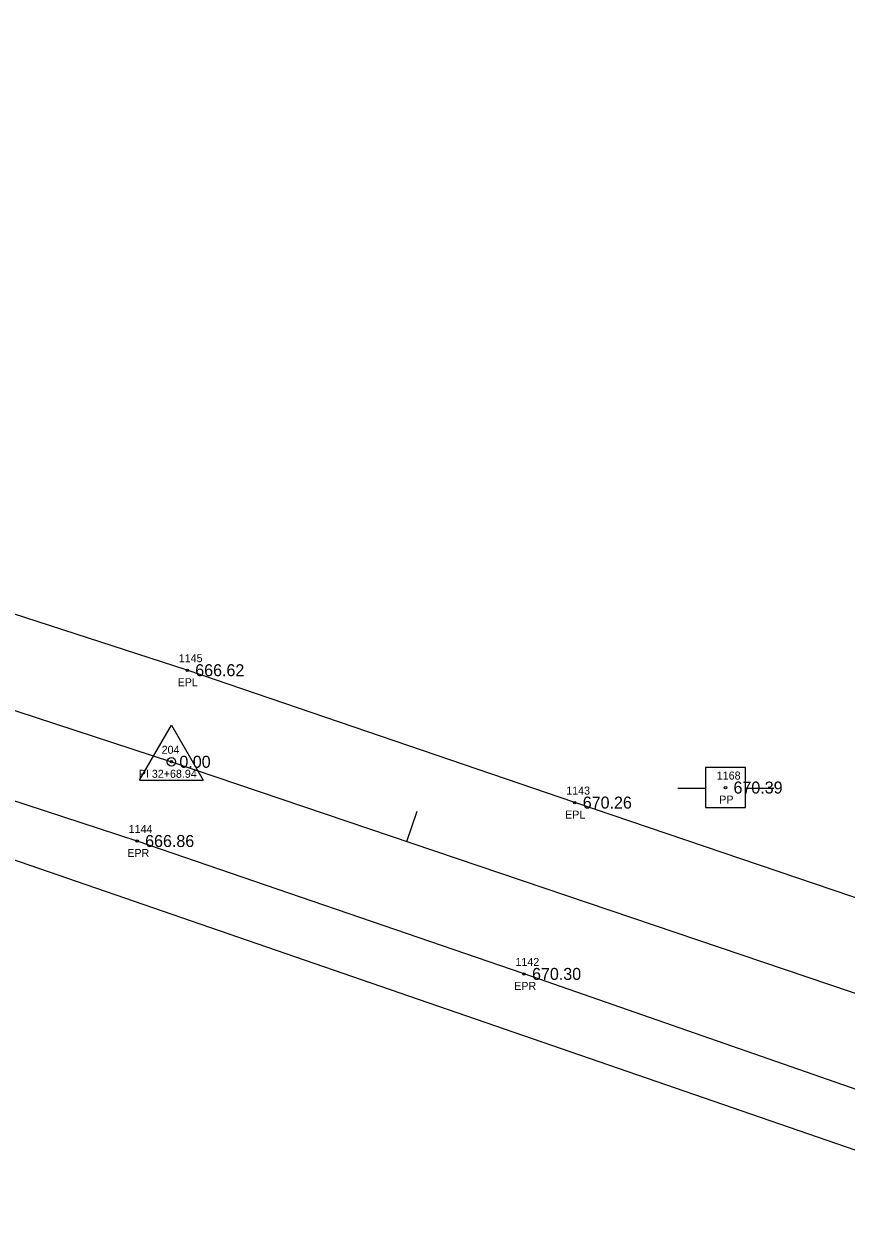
# Model space of a CAD drawing. Extents: x 1655137 to 1657928, y 1003994 to 1005407.
# Drawn here: x 1656606.1 to 1656708.9, y 1004485.2 to 1004634.6 of the extents above; entities that cross this region are included whole.
import ezdxf

# ---------------------------------------------------------------- set-up
doc = ezdxf.new("R2010")
doc.units = 0
for name, color, linetype in [('RD_EX_Road', 7, 'Continuous'), ('RD_EX_Road_txCode', 7, 'Continuous'), ('RD_EX_TX_Road_ELEV', 7, 'Continuous'), ('RD_EX_UT', 7, 'Continuous'), ('RD_EX_UT_txCode', 7, 'Continuous'), ('RD_EX_VEG', 7, 'Continuous'), ('RD_HC_Cl', 7, 'Continuous'), ('RD_HC_Data', 7, 'Continuous'), ('RD_HC_Data_Tic', 7, 'Continuous'), ('RD_HC_Survey_ELEV', 7, 'Continuous'), ('RD_HC_txCode', 7, 'Continuous'), ('RD_SMD_Locator', 7, 'Continuous')]:
    doc.layers.add(name, color=color, linetype=linetype)

msp = doc.modelspace()

# ---------------------------------------------------------------- linework, layer by layer
at = {"layer": 'RD_EX_Road'}
for points in [[(1657064.39, 1004409.09), (1657015.67, 1004424.64), (1656965.82, 1004440.6), (1656917.99, 1004455.95), (1656868.5, 1004471.86), (1656826.53, 1004486.06), (1656801.74, 1004494.51), (1656772.14, 1004504.27), (1656723.45, 1004520.92), (1656674.94, 1004537.34), (1656626.5, 1004553.88), (1656578.27, 1004569.52), (1656529.18, 1004584.75), (1656481.5, 1004600.51), (1656432.67, 1004617.14), (1656404.34, 1004625.82)], [(1657057.77, 1004388.92), (1657009.7, 1004404.08), (1656958.18, 1004419.84), (1656956.49, 1004419.67), (1656924.83, 1004429.55), (1656916.51, 1004432.8), (1656911.19, 1004434.68), (1656862.46, 1004450.21), (1656813.53, 1004466.42), (1656765.51, 1004482.33), (1656716.81, 1004499.14), (1656668.6, 1004515.93), (1656620.24, 1004532.54), (1656571.72, 1004548.37), (1656523.3, 1004563.77), (1656474.37, 1004580.29), (1656426.43, 1004596.82), (1656398.22, 1004606.78)]]:
    msp.add_lwpolyline(points, dxfattribs=at)
at = {"layer": 'RD_EX_UT'}
for p, q in [((1656696.27, 1004541.73), (1656691.27, 1004541.73)), ((1656691.27, 1004541.73), (1656691.27, 1004536.73)), ((1656696.27, 1004536.73), (1656696.27, 1004541.73)), ((1656687.84, 1004539.16), (1656691.31, 1004539.16)), ((1656696.2, 1004539.16), (1656699.84, 1004539.16)), ((1656691.27, 1004536.73), (1656696.27, 1004536.73))]:
    msp.add_line(p, q, dxfattribs=at)
at = {"layer": 'RD_EX_VEG'}
msp.add_lwpolyline([(1656891.08, 1004405.37), (1656915.13, 1004420.4), (1656763.49, 1004475.48), (1656570, 1004542.2), (1656467.82, 1004565.09), (1656367.55, 1004594.62), (1656280.9, 1004634.63), (1656273.57, 1004608.65)], dxfattribs=at)
at = {"layer": 'RD_HC_Cl'}
for p, q in [((1656507.36, 1004580.77), (1656624.52, 1004542.44)), ((1656624.52, 1004542.44), (1656857.94, 1004463.43))]:
    msp.add_line(p, q, dxfattribs=at)
at = {"layer": 'RD_HC_Data'}
for p, q in [((1656620.55, 1004540.15), (1656624.53, 1004547.03)), ((1656624.53, 1004547.03), (1656628.49, 1004540.15)), ((1656620.55, 1004540.15), (1656628.49, 1004540.15))]:
    msp.add_line(p, q, dxfattribs=at)
msp.add_circle((1656624.52, 1004542.44), 0.529, dxfattribs=at)
at = {"layer": 'RD_HC_Data_Tic'}
msp.add_line((1656653.94, 1004532.49), (1656655.22, 1004536.27), dxfattribs=at)
at = {"layer": 'RD_SMD_Locator'}
for centre in [(1656626.5, 1004553.88), (1656624.52, 1004542.44), (1656693.78, 1004539.22), (1656674.94, 1004537.34), (1656620.24, 1004532.54), (1656668.6, 1004515.93)]:
    msp.add_circle(centre, 0.15, dxfattribs=at)

# ---------------------------------------------------------------- texts
at = {"layer": 'RD_EX_Road_txCode'}
for s, p in [('1145', (1656625.44, 1004554.88)), ('EPL', (1656625.3, 1004551.88)), ('1143', (1656673.87, 1004538.34)), ('EPL', (1656673.73, 1004535.34)), ('1144', (1656619.18, 1004533.54)), ('EPR', (1656619.01, 1004530.54)), ('1142', (1656667.53, 1004516.93)), ('EPR', (1656667.37, 1004513.93))]:
    msp.add_text(s, height=1, dxfattribs=at).set_placement(p)
at = {"layer": 'RD_EX_TX_Road_ELEV'}
for s, p in [('666.62', (1656627.5, 1004553.13)), ('670.26', (1656675.94, 1004536.59)), ('666.86', (1656621.24, 1004531.79)), ('670.30', (1656669.6, 1004515.18))]:
    msp.add_text(s, height=1.5, dxfattribs=at).set_placement(p)
at = {"layer": 'RD_EX_UT_txCode'}
for s, p in [('1168', (1656692.69, 1004540.22)), ('PP', (1656693, 1004537.22))]:
    msp.add_text(s, height=1, dxfattribs=at).set_placement(p)
at = {"layer": 'RD_HC_Survey_ELEV'}
for s, p in [('0.00', (1656625.52, 1004541.69)), ('670.39', (1656694.78, 1004538.47))]:
    msp.add_text(s, height=1.5, dxfattribs=at).set_placement(p)
at = {"layer": 'RD_HC_txCode'}
for s, p in [('204', (1656623.3, 1004543.44)), ('PI 32+68.94', (1656620.44, 1004540.44))]:
    msp.add_text(s, height=1, dxfattribs=at).set_placement(p)

doc.saveas('drawing.dxf')
